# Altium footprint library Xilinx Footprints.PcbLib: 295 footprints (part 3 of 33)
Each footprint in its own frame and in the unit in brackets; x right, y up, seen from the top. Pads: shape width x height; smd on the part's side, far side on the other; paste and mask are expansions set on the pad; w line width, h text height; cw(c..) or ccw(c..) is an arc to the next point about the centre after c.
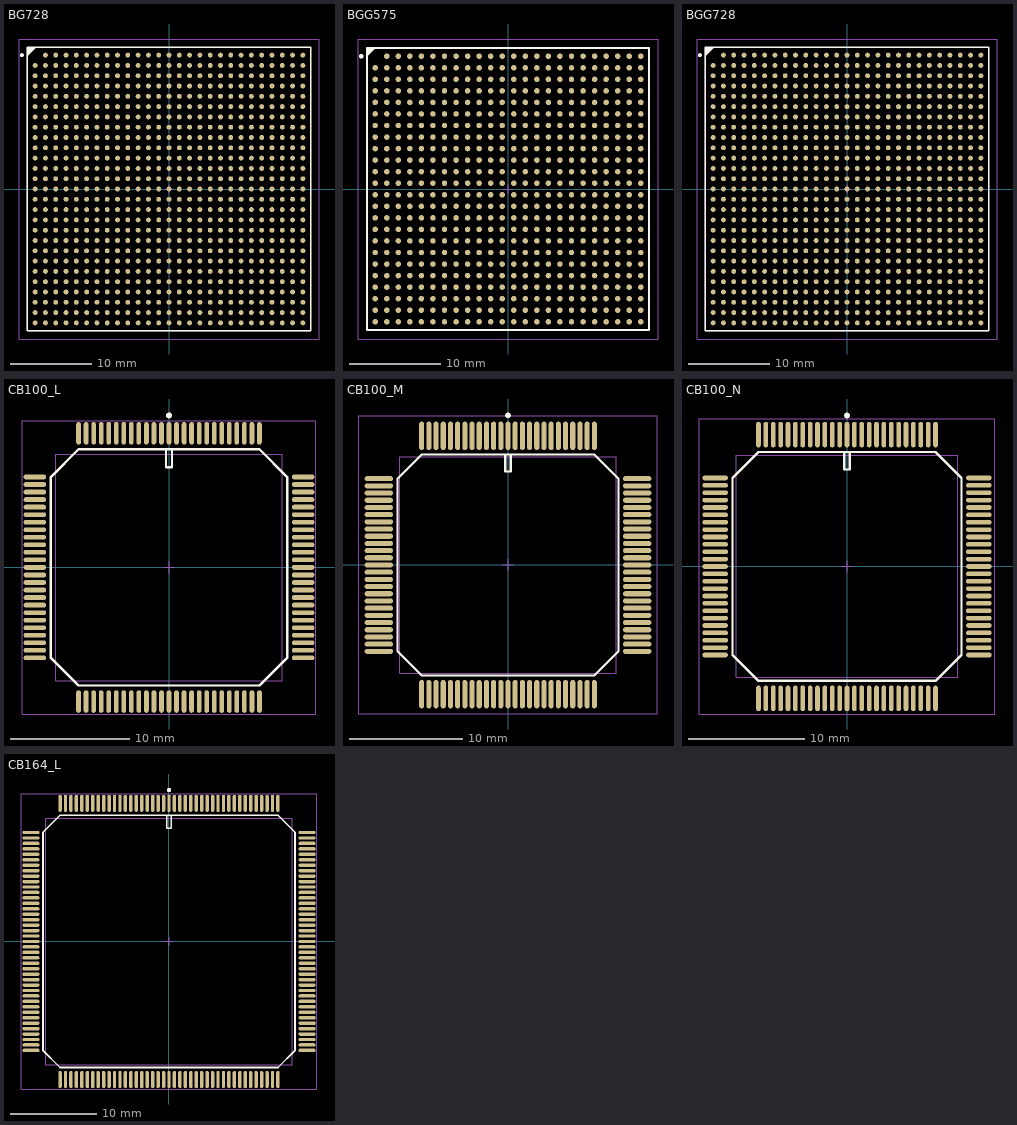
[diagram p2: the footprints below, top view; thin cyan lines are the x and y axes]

## BG728 [mm] "728-Ball Plastic Ball Grid Array (BG728)"
height 2.6
pads (728):
  round 0.6 smd: A2(-15.24,16.51) A3(-13.97,16.51) A4(-12.7,16.51) A5(-11.43,16.51) A6(-10.16,16.51) A7(-8.89,16.51) A8(-7.62,16.51) A9(-6.35,16.51) A10(-5.08,16.51) A11(-3.81,16.51) A12(-2.54,16.51) A13(-1.27,16.51) A14(0,16.51) A15(1.27,16.51) A16(2.54,16.51) A17(3.81,16.51) A18(5.08,16.51) A19(6.35,16.51) A20(7.62,16.51) A21(8.89,16.51) A22(10.16,16.51) A23(11.43,16.51) A24(12.7,16.51) A25(13.97,16.51) A26(15.24,16.51) A27(16.51,16.51) AA1(-16.51,-8.89) AA2(-15.24,-8.89) AA3(-13.97,-8.89) AA4(-12.7,-8.89) AA5(-11.43,-8.89) AA6(-10.16,-8.89) AA7(-8.89,-8.89) AA8(-7.62,-8.89) AA9(-6.35,-8.89) AA10(-5.08,-8.89) AA11(-3.81,-8.89) AA12(-2.54,-8.89) AA13(-1.27,-8.89) AA14(0,-8.89) AA15(1.27,-8.89) AA16(2.54,-8.89) AA17(3.81,-8.89) AA18(5.08,-8.89) AA19(6.35,-8.89) AA20(7.62,-8.89) AA21(8.89,-8.89) AA22(10.16,-8.89) AA23(11.43,-8.89) AA24(12.7,-8.89) AA25(13.97,-8.89) AA26(15.24,-8.89) AA27(16.51,-8.89) AB1(-16.51,-10.16) AB2(-15.24,-10.16) AB3(-13.97,-10.16) AB4(-12.7,-10.16) AB5(-11.43,-10.16) AB6(-10.16,-10.16) AB7(-8.89,-10.16) AB8(-7.62,-10.16) AB9(-6.35,-10.16) AB10(-5.08,-10.16) AB11(-3.81,-10.16) AB12(-2.54,-10.16) AB13(-1.27,-10.16) AB14(0,-10.16) AB15(1.27,-10.16) AB16(2.54,-10.16) AB17(3.81,-10.16) AB18(5.08,-10.16) AB19(6.35,-10.16) AB20(7.62,-10.16) AB21(8.89,-10.16) AB22(10.16,-10.16) AB23(11.43,-10.16) AB24(12.7,-10.16) AB25(13.97,-10.16) AB26(15.24,-10.16) AB27(16.51,-10.16) AC1(-16.51,-11.43) AC2(-15.24,-11.43) AC3(-13.97,-11.43) AC4(-12.7,-11.43) AC5(-11.43,-11.43) AC6(-10.16,-11.43) AC7(-8.89,-11.43) AC8(-7.62,-11.43) AC9(-6.35,-11.43) AC10(-5.08,-11.43) AC11(-3.81,-11.43) AC12(-2.54,-11.43) AC13(-1.27,-11.43) AC14(0,-11.43) AC15(1.27,-11.43) AC16(2.54,-11.43) AC17(3.81,-11.43) AC18(5.08,-11.43) AC19(6.35,-11.43) AC20(7.62,-11.43) AC21(8.89,-11.43) AC22(10.16,-11.43) AC23(11.43,-11.43) AC24(12.7,-11.43) AC25(13.97,-11.43) AC26(15.24,-11.43) AC27(16.51,-11.43) AD1(-16.51,-12.7) AD2(-15.24,-12.7) AD3(-13.97,-12.7) AD4(-12.7,-12.7) AD5(-11.43,-12.7) AD6(-10.16,-12.7) AD7(-8.89,-12.7) AD8(-7.62,-12.7) AD9(-6.35,-12.7) AD10(-5.08,-12.7) AD11(-3.81,-12.7) AD12(-2.54,-12.7) AD13(-1.27,-12.7) AD14(0,-12.7) AD15(1.27,-12.7) AD16(2.54,-12.7) AD17(3.81,-12.7) AD18(5.08,-12.7) AD19(6.35,-12.7) AD20(7.62,-12.7) AD21(8.89,-12.7) AD22(10.16,-12.7) AD23(11.43,-12.7) AD24(12.7,-12.7) AD25(13.97,-12.7) AD26(15.24,-12.7) AD27(16.51,-12.7) AE1(-16.51,-13.97) AE2(-15.24,-13.97) AE3(-13.97,-13.97) AE4(-12.7,-13.97) AE5(-11.43,-13.97) AE6(-10.16,-13.97) AE7(-8.89,-13.97) AE8(-7.62,-13.97) AE9(-6.35,-13.97) AE10(-5.08,-13.97) AE11(-3.81,-13.97) AE12(-2.54,-13.97) AE13(-1.27,-13.97) AE14(0,-13.97) AE15(1.27,-13.97) AE16(2.54,-13.97) AE17(3.81,-13.97) AE18(5.08,-13.97) AE19(6.35,-13.97) AE20(7.62,-13.97) AE21(8.89,-13.97) AE22(10.16,-13.97) AE23(11.43,-13.97) AE24(12.7,-13.97) AE25(13.97,-13.97) AE26(15.24,-13.97) AE27(16.51,-13.97) AF1(-16.51,-15.24) AF2(-15.24,-15.24) AF3(-13.97,-15.24) AF4(-12.7,-15.24) AF5(-11.43,-15.24) AF6(-10.16,-15.24) AF7(-8.89,-15.24) AF8(-7.62,-15.24) AF9(-6.35,-15.24) AF10(-5.08,-15.24) AF11(-3.81,-15.24) AF12(-2.54,-15.24) AF13(-1.27,-15.24) AF14(0,-15.24) AF15(1.27,-15.24) AF16(2.54,-15.24) AF17(3.81,-15.24) AF18(5.08,-15.24) AF19(6.35,-15.24) AF20(7.62,-15.24) AF21(8.89,-15.24) AF22(10.16,-15.24) AF23(11.43,-15.24) AF24(12.7,-15.24) AF25(13.97,-15.24) AF26(15.24,-15.24) AF27(16.51,-15.24) AG1(-16.51,-16.51) AG2(-15.24,-16.51) AG3(-13.97,-16.51) AG4(-12.7,-16.51) AG5(-11.43,-16.51) AG6(-10.16,-16.51) AG7(-8.89,-16.51) AG8(-7.62,-16.51) AG9(-6.35,-16.51) AG10(-5.08,-16.51) AG11(-3.81,-16.51) AG12(-2.54,-16.51) AG13(-1.27,-16.51) AG14(0,-16.51) AG15(1.27,-16.51) AG16(2.54,-16.51) AG17(3.81,-16.51) AG18(5.08,-16.51) AG19(6.35,-16.51) AG20(7.62,-16.51) AG21(8.89,-16.51) AG22(10.16,-16.51) AG23(11.43,-16.51) AG24(12.7,-16.51) AG25(13.97,-16.51) AG26(15.24,-16.51) AG27(16.51,-16.51) B1(-16.51,15.24) B2(-15.24,15.24) B3(-13.97,15.24) B4(-12.7,15.24) B5(-11.43,15.24) B6(-10.16,15.24) B7(-8.89,15.24) B8(-7.62,15.24) B9(-6.35,15.24) B10(-5.08,15.24) B11(-3.81,15.24) B12(-2.54,15.24) B13(-1.27,15.24) B14(0,15.24) B15(1.27,15.24) B16(2.54,15.24) B17(3.81,15.24) B18(5.08,15.24) B19(6.35,15.24) B20(7.62,15.24) B21(8.89,15.24) B22(10.16,15.24) B23(11.43,15.24) B24(12.7,15.24) B25(13.97,15.24) B26(15.24,15.24) B27(16.51,15.24) C1(-16.51,13.97) C2(-15.24,13.97) C3(-13.97,13.97) C4(-12.7,13.97) C5(-11.43,13.97) C6(-10.16,13.97) C7(-8.89,13.97) C8(-7.62,13.97) C9(-6.35,13.97) C10(-5.08,13.97) C11(-3.81,13.97) C12(-2.54,13.97) C13(-1.27,13.97) C14(0,13.97) C15(1.27,13.97) C16(2.54,13.97) C17(3.81,13.97) C18(5.08,13.97) C19(6.35,13.97) C20(7.62,13.97) C21(8.89,13.97) C22(10.16,13.97) C23(11.43,13.97) C24(12.7,13.97) C25(13.97,13.97) C26(15.24,13.97) C27(16.51,13.97) D1(-16.51,12.7) D2(-15.24,12.7) D3(-13.97,12.7) D4(-12.7,12.7) D5(-11.43,12.7) D6(-10.16,12.7) D7(-8.89,12.7) D8(-7.62,12.7) D9(-6.35,12.7) D10(-5.08,12.7) D11(-3.81,12.7) D12(-2.54,12.7) D13(-1.27,12.7) D14(0,12.7) D15(1.27,12.7) D16(2.54,12.7) D17(3.81,12.7) D18(5.08,12.7) D19(6.35,12.7) D20(7.62,12.7) D21(8.89,12.7) D22(10.16,12.7) D23(11.43,12.7) D24(12.7,12.7) D25(13.97,12.7) D26(15.24,12.7) D27(16.51,12.7) E1(-16.51,11.43) E2(-15.24,11.43) E3(-13.97,11.43) E4(-12.7,11.43) E5(-11.43,11.43) E6(-10.16,11.43) E7(-8.89,11.43) E8(-7.62,11.43) E9(-6.35,11.43) E10(-5.08,11.43) E11(-3.81,11.43) E12(-2.54,11.43) E13(-1.27,11.43) E14(0,11.43) E15(1.27,11.43) E16(2.54,11.43) E17(3.81,11.43) E18(5.08,11.43) E19(6.35,11.43) E20(7.62,11.43) E21(8.89,11.43) E22(10.16,11.43) E23(11.43,11.43) E24(12.7,11.43) E25(13.97,11.43) E26(15.24,11.43) E27(16.51,11.43) F1(-16.51,10.16) F2(-15.24,10.16) F3(-13.97,10.16) F4(-12.7,10.16) F5(-11.43,10.16) F6(-10.16,10.16) F7(-8.89,10.16) F8(-7.62,10.16) F9(-6.35,10.16) F10(-5.08,10.16) F11(-3.81,10.16) F12(-2.54,10.16) F13(-1.27,10.16) F14(0,10.16) F15(1.27,10.16) F16(2.54,10.16) F17(3.81,10.16) F18(5.08,10.16) F19(6.35,10.16) F20(7.62,10.16) F21(8.89,10.16) F22(10.16,10.16) F23(11.43,10.16) F24(12.7,10.16) F25(13.97,10.16) F26(15.24,10.16) F27(16.51,10.16) G1(-16.51,8.89) G2(-15.24,8.89) G3(-13.97,8.89) G4(-12.7,8.89) G5(-11.43,8.89) G6(-10.16,8.89) G7(-8.89,8.89) G8(-7.62,8.89) G9(-6.35,8.89) G10(-5.08,8.89) G11(-3.81,8.89) G12(-2.54,8.89) G13(-1.27,8.89) G14(0,8.89) G15(1.27,8.89) G16(2.54,8.89) G17(3.81,8.89) G18(5.08,8.89) G19(6.35,8.89) G20(7.62,8.89) G21(8.89,8.89) G22(10.16,8.89) G23(11.43,8.89) G24(12.7,8.89) G25(13.97,8.89) G26(15.24,8.89) G27(16.51,8.89) H1(-16.51,7.62) H2(-15.24,7.62) H3(-13.97,7.62) H4(-12.7,7.62) H5(-11.43,7.62) H6(-10.16,7.62) H7(-8.89,7.62) H8(-7.62,7.62) H9(-6.35,7.62) H10(-5.08,7.62) H11(-3.81,7.62) H12(-2.54,7.62) H13(-1.27,7.62) H14(0,7.62) H15(1.27,7.62) H16(2.54,7.62) H17(3.81,7.62) H18(5.08,7.62) H19(6.35,7.62) H20(7.62,7.62) H21(8.89,7.62) H22(10.16,7.62) H23(11.43,7.62) H24(12.7,7.62) H25(13.97,7.62) H26(15.24,7.62) H27(16.51,7.62) J1(-16.51,6.35) J2(-15.24,6.35) J3(-13.97,6.35) J4(-12.7,6.35) J5(-11.43,6.35) J6(-10.16,6.35) J7(-8.89,6.35) J8(-7.62,6.35) J9(-6.35,6.35) J10(-5.08,6.35) J11(-3.81,6.35) J12(-2.54,6.35) J13(-1.27,6.35) J14(0,6.35) J15(1.27,6.35) J16(2.54,6.35) J17(3.81,6.35) J18(5.08,6.35) J19(6.35,6.35) J20(7.62,6.35) J21(8.89,6.35) J22(10.16,6.35) J23(11.43,6.35) J24(12.7,6.35) J25(13.97,6.35) J26(15.24,6.35) J27(16.51,6.35) K1(-16.51,5.08) K2(-15.24,5.08) K3(-13.97,5.08) K4(-12.7,5.08) K5(-11.43,5.08) K6(-10.16,5.08) K7(-8.89,5.08) K8(-7.62,5.08) K9(-6.35,5.08) K10(-5.08,5.08) K11(-3.81,5.08) K12(-2.54,5.08) K13(-1.27,5.08) K14(0,5.08) K15(1.27,5.08) K16(2.54,5.08) K17(3.81,5.08) K18(5.08,5.08) K19(6.35,5.08) K20(7.62,5.08) K21(8.89,5.08) K22(10.16,5.08) K23(11.43,5.08) K24(12.7,5.08) K25(13.97,5.08) K26(15.24,5.08) K27(16.51,5.08) L1(-16.51,3.81) L2(-15.24,3.81) L3(-13.97,3.81) L4(-12.7,3.81) L5(-11.43,3.81) L6(-10.16,3.81) L7(-8.89,3.81) L8(-7.62,3.81) L9(-6.35,3.81) L10(-5.08,3.81) L11(-3.81,3.81) L12(-2.54,3.81) L13(-1.27,3.81) L14(0,3.81) L15(1.27,3.81) L16(2.54,3.81) L17(3.81,3.81) L18(5.08,3.81) L19(6.35,3.81) L20(7.62,3.81) L21(8.89,3.81) L22(10.16,3.81) L23(11.43,3.81) L24(12.7,3.81) L25(13.97,3.81) L26(15.24,3.81) L27(16.51,3.81) M1(-16.51,2.54) M2(-15.24,2.54) M3(-13.97,2.54) M4(-12.7,2.54) M5(-11.43,2.54) M6(-10.16,2.54) M7(-8.89,2.54) M8(-7.62,2.54) M9(-6.35,2.54) M10(-5.08,2.54) M11(-3.81,2.54) M12(-2.54,2.54) M13(-1.27,2.54) M14(0,2.54) M15(1.27,2.54) M16(2.54,2.54) M17(3.81,2.54) M18(5.08,2.54) M19(6.35,2.54) M20(7.62,2.54) M21(8.89,2.54) M22(10.16,2.54) M23(11.43,2.54) M24(12.7,2.54) M25(13.97,2.54) M26(15.24,2.54) M27(16.51,2.54) N1(-16.51,1.27) N2(-15.24,1.27) N3(-13.97,1.27) N4(-12.7,1.27) N5(-11.43,1.27) N6(-10.16,1.27) N7(-8.89,1.27) N8(-7.62,1.27) N9(-6.35,1.27) N10(-5.08,1.27) N11(-3.81,1.27) N12(-2.54,1.27) N13(-1.27,1.27) N14(0,1.27) N15(1.27,1.27) N16(2.54,1.27) N17(3.81,1.27) N18(5.08,1.27) N19(6.35,1.27) N20(7.62,1.27) N21(8.89,1.27) N22(10.16,1.27) N23(11.43,1.27) N24(12.7,1.27) N25(13.97,1.27) N26(15.24,1.27) N27(16.51,1.27) P1(-16.51,0) P2(-15.24,0) P3(-13.97,0) P4(-12.7,0) P5(-11.43,0) P6(-10.16,0) P7(-8.89,0) P8(-7.62,0) P9(-6.35,0) P10(-5.08,0) P11(-3.81,0) P12(-2.54,0) P13(-1.27,0) P14(0,0) P15(1.27,0) P16(2.54,0) P17(3.81,0) P18(5.08,0) P19(6.35,0) P20(7.62,0) P21(8.89,0) P22(10.16,0) P23(11.43,0) P24(12.7,0) P25(13.97,0) P26(15.24,0) P27(16.51,0) R1(-16.51,-1.27) R2(-15.24,-1.27) R3(-13.97,-1.27) R4(-12.7,-1.27) R5(-11.43,-1.27) R6(-10.16,-1.27) R7(-8.89,-1.27) R8(-7.62,-1.27) R9(-6.35,-1.27) R10(-5.08,-1.27) R11(-3.81,-1.27) R12(-2.54,-1.27) R13(-1.27,-1.27) R14(0,-1.27) R15(1.27,-1.27) R16(2.54,-1.27) R17(3.81,-1.27) R18(5.08,-1.27) R19(6.35,-1.27) R20(7.62,-1.27) R21(8.89,-1.27) R22(10.16,-1.27) R23(11.43,-1.27) R24(12.7,-1.27) R25(13.97,-1.27) R26(15.24,-1.27) R27(16.51,-1.27) T1(-16.51,-2.54) T2(-15.24,-2.54) T3(-13.97,-2.54) T4(-12.7,-2.54) T5(-11.43,-2.54) T6(-10.16,-2.54) T7(-8.89,-2.54) T8(-7.62,-2.54) T9(-6.35,-2.54) T10(-5.08,-2.54) T11(-3.81,-2.54) T12(-2.54,-2.54) T13(-1.27,-2.54) T14(0,-2.54) T15(1.27,-2.54) T16(2.54,-2.54) T17(3.81,-2.54) T18(5.08,-2.54) T19(6.35,-2.54) T20(7.62,-2.54) T21(8.89,-2.54) T22(10.16,-2.54) T23(11.43,-2.54) T24(12.7,-2.54) T25(13.97,-2.54) T26(15.24,-2.54) T27(16.51,-2.54) U1(-16.51,-3.81) U2(-15.24,-3.81) U3(-13.97,-3.81) U4(-12.7,-3.81) U5(-11.43,-3.81) U6(-10.16,-3.81) U7(-8.89,-3.81) U8(-7.62,-3.81) U9(-6.35,-3.81) U10(-5.08,-3.81) U11(-3.81,-3.81) U12(-2.54,-3.81) U13(-1.27,-3.81) U14(0,-3.81) U15(1.27,-3.81) U16(2.54,-3.81) U17(3.81,-3.81) U18(5.08,-3.81) U19(6.35,-3.81) U20(7.62,-3.81) U21(8.89,-3.81) U22(10.16,-3.81) U23(11.43,-3.81) U24(12.7,-3.81) U25(13.97,-3.81) U26(15.24,-3.81) U27(16.51,-3.81) V1(-16.51,-5.08) V2(-15.24,-5.08) V3(-13.97,-5.08) V4(-12.7,-5.08) V5(-11.43,-5.08) V6(-10.16,-5.08) V7(-8.89,-5.08) V8(-7.62,-5.08) V9(-6.35,-5.08) V10(-5.08,-5.08) V11(-3.81,-5.08) V12(-2.54,-5.08) V13(-1.27,-5.08) V14(0,-5.08) V15(1.27,-5.08) V16(2.54,-5.08) V17(3.81,-5.08) V18(5.08,-5.08) V19(6.35,-5.08) V20(7.62,-5.08) V21(8.89,-5.08) V22(10.16,-5.08) V23(11.43,-5.08) V24(12.7,-5.08) V25(13.97,-5.08) V26(15.24,-5.08) V27(16.51,-5.08) W1(-16.51,-6.35) W2(-15.24,-6.35) W3(-13.97,-6.35) W4(-12.7,-6.35) W5(-11.43,-6.35) W6(-10.16,-6.35) W7(-8.89,-6.35) W8(-7.62,-6.35) W9(-6.35,-6.35) W10(-5.08,-6.35) W11(-3.81,-6.35) W12(-2.54,-6.35) W13(-1.27,-6.35) W14(0,-6.35) W15(1.27,-6.35) W16(2.54,-6.35) W17(3.81,-6.35) W18(5.08,-6.35) W19(6.35,-6.35) W20(7.62,-6.35) W21(8.89,-6.35) W22(10.16,-6.35) W23(11.43,-6.35) W24(12.7,-6.35) W25(13.97,-6.35) W26(15.24,-6.35) W27(16.51,-6.35) Y1(-16.51,-7.62) Y2(-15.24,-7.62) Y3(-13.97,-7.62) Y4(-12.7,-7.62) Y5(-11.43,-7.62) Y6(-10.16,-7.62) Y7(-8.89,-7.62) Y8(-7.62,-7.62) Y9(-6.35,-7.62) Y10(-5.08,-7.62) Y11(-3.81,-7.62) Y12(-2.54,-7.62) Y13(-1.27,-7.62) Y14(0,-7.62) Y15(1.27,-7.62) Y16(2.54,-7.62) Y17(3.81,-7.62) Y18(5.08,-7.62) Y19(6.35,-7.62) Y20(7.62,-7.62) Y21(8.89,-7.62) Y22(10.16,-7.62) Y23(11.43,-7.62) Y24(12.7,-7.62) Y25(13.97,-7.62) Y26(15.24,-7.62) Y27(16.51,-7.62)
Top Overlay:
  circle w0.25: c-18.15,16.51 r0.125
  region: -16.51,17.5 -17.5,16.51 -17.5,17.5
  lines w0.2: -17.5,16.51 -16.51,17.5 ; -17.5,-17.5 17.5,-17.5 17.5,17.5 -17.5,17.5 -17.5,-17.5
Mechanical 13:
  lines w0.1: -17.5,-17.5 17.5,-17.5 17.5,17.5 -17.5,17.5 -17.5,-17.5
Mechanical 15:
  lines w0.1: -0.5,0 0.5,0 ; 0,-0.5 0,0.5 ; -18.5,-18.5 18.5,-18.5 18.5,18.5 -18.5,18.5 -18.5,-18.5
3D body: height 2.6, standoff 0, extent -17.5,-17.5 17.5,17.5

## BGG575 [mm] "575-Ball Molded Ball Grid Array (BGG575) - Pb-Free"
height 2.6
pads (575):
  round 0.6 smd: A2(-13.335,14.605) A3(-12.065,14.605) A4(-10.795,14.605) A5(-9.525,14.605) A6(-8.255,14.605) A7(-6.985,14.605) A8(-5.715,14.605) A9(-4.445,14.605) A10(-3.175,14.605) A11(-1.905,14.605) A12(-0.635,14.605) A13(0.635,14.605) A14(1.905,14.605) A15(3.175,14.605) A16(4.445,14.605) A17(5.715,14.605) A18(6.985,14.605) A19(8.255,14.605) A20(9.525,14.605) A21(10.795,14.605) A22(12.065,14.605) A23(13.335,14.605) A24(14.605,14.605) AA1(-14.605,-10.795) AA2(-13.335,-10.795) AA3(-12.065,-10.795) AA4(-10.795,-10.795) AA5(-9.525,-10.795) AA6(-8.255,-10.795) AA7(-6.985,-10.795) AA8(-5.715,-10.795) AA9(-4.445,-10.795) AA10(-3.175,-10.795) AA11(-1.905,-10.795) AA12(-0.635,-10.795) AA13(0.635,-10.795) AA14(1.905,-10.795) AA15(3.175,-10.795) AA16(4.445,-10.795) AA17(5.715,-10.795) AA18(6.985,-10.795) AA19(8.255,-10.795) AA20(9.525,-10.795) AA21(10.795,-10.795) AA22(12.065,-10.795) AA23(13.335,-10.795) AA24(14.605,-10.795) AB1(-14.605,-12.065) AB2(-13.335,-12.065) AB3(-12.065,-12.065) AB4(-10.795,-12.065) AB5(-9.525,-12.065) AB6(-8.255,-12.065) AB7(-6.985,-12.065) AB8(-5.715,-12.065) AB9(-4.445,-12.065) AB10(-3.175,-12.065) AB11(-1.905,-12.065) AB12(-0.635,-12.065) AB13(0.635,-12.065) AB14(1.905,-12.065) AB15(3.175,-12.065) AB16(4.445,-12.065) AB17(5.715,-12.065) AB18(6.985,-12.065) AB19(8.255,-12.065) AB20(9.525,-12.065) AB21(10.795,-12.065) AB22(12.065,-12.065) AB23(13.335,-12.065) AB24(14.605,-12.065) AC1(-14.605,-13.335) AC2(-13.335,-13.335) AC3(-12.065,-13.335) AC4(-10.795,-13.335) AC5(-9.525,-13.335) AC6(-8.255,-13.335) AC7(-6.985,-13.335) AC8(-5.715,-13.335) AC9(-4.445,-13.335) AC10(-3.175,-13.335) AC11(-1.905,-13.335) AC12(-0.635,-13.335) AC13(0.635,-13.335) AC14(1.905,-13.335) AC15(3.175,-13.335) AC16(4.445,-13.335) AC17(5.715,-13.335) AC18(6.985,-13.335) AC19(8.255,-13.335) AC20(9.525,-13.335) AC21(10.795,-13.335) AC22(12.065,-13.335) AC23(13.335,-13.335) AC24(14.605,-13.335) AD1(-14.605,-14.605) AD2(-13.335,-14.605) AD3(-12.065,-14.605) AD4(-10.795,-14.605) AD5(-9.525,-14.605) AD6(-8.255,-14.605) AD7(-6.985,-14.605) AD8(-5.715,-14.605) AD9(-4.445,-14.605) AD10(-3.175,-14.605) AD11(-1.905,-14.605) AD12(-0.635,-14.605) AD13(0.635,-14.605) AD14(1.905,-14.605) AD15(3.175,-14.605) AD16(4.445,-14.605) AD17(5.715,-14.605) AD18(6.985,-14.605) AD19(8.255,-14.605) AD20(9.525,-14.605) AD21(10.795,-14.605) AD22(12.065,-14.605) AD23(13.335,-14.605) AD24(14.605,-14.605) B1(-14.605,13.335) B2(-13.335,13.335) B3(-12.065,13.335) B4(-10.795,13.335) B5(-9.525,13.335) B6(-8.255,13.335) B7(-6.985,13.335) B8(-5.715,13.335) B9(-4.445,13.335) B10(-3.175,13.335) B11(-1.905,13.335) B12(-0.635,13.335) B13(0.635,13.335) B14(1.905,13.335) B15(3.175,13.335) B16(4.445,13.335) B17(5.715,13.335) B18(6.985,13.335) B19(8.255,13.335) B20(9.525,13.335) B21(10.795,13.335) B22(12.065,13.335) B23(13.335,13.335) B24(14.605,13.335) C1(-14.605,12.065) C2(-13.335,12.065) C3(-12.065,12.065) C4(-10.795,12.065) C5(-9.525,12.065) C6(-8.255,12.065) C7(-6.985,12.065) C8(-5.715,12.065) C9(-4.445,12.065) C10(-3.175,12.065) C11(-1.905,12.065) C12(-0.635,12.065) C13(0.635,12.065) C14(1.905,12.065) C15(3.175,12.065) C16(4.445,12.065) C17(5.715,12.065) C18(6.985,12.065) C19(8.255,12.065) C20(9.525,12.065) C21(10.795,12.065) C22(12.065,12.065) C23(13.335,12.065) C24(14.605,12.065) D1(-14.605,10.795) D2(-13.335,10.795) D3(-12.065,10.795) D4(-10.795,10.795) D5(-9.525,10.795) D6(-8.255,10.795) D7(-6.985,10.795) D8(-5.715,10.795) D9(-4.445,10.795) D10(-3.175,10.795) D11(-1.905,10.795) D12(-0.635,10.795) D13(0.635,10.795) D14(1.905,10.795) D15(3.175,10.795) D16(4.445,10.795) D17(5.715,10.795) D18(6.985,10.795) D19(8.255,10.795) D20(9.525,10.795) D21(10.795,10.795) D22(12.065,10.795) D23(13.335,10.795) D24(14.605,10.795) E1(-14.605,9.525) E2(-13.335,9.525) E3(-12.065,9.525) E4(-10.795,9.525) E5(-9.525,9.525) E6(-8.255,9.525) E7(-6.985,9.525) E8(-5.715,9.525) E9(-4.445,9.525) E10(-3.175,9.525) E11(-1.905,9.525) E12(-0.635,9.525) E13(0.635,9.525) E14(1.905,9.525) E15(3.175,9.525) E16(4.445,9.525) E17(5.715,9.525) E18(6.985,9.525) E19(8.255,9.525) E20(9.525,9.525) E21(10.795,9.525) E22(12.065,9.525) E23(13.335,9.525) E24(14.605,9.525) F1(-14.605,8.255) F2(-13.335,8.255) F3(-12.065,8.255) F4(-10.795,8.255) F5(-9.525,8.255) F6(-8.255,8.255) F7(-6.985,8.255) F8(-5.715,8.255) F9(-4.445,8.255) F10(-3.175,8.255) F11(-1.905,8.255) F12(-0.635,8.255) F13(0.635,8.255) F14(1.905,8.255) F15(3.175,8.255) F16(4.445,8.255) F17(5.715,8.255) F18(6.985,8.255) F19(8.255,8.255) F20(9.525,8.255) F21(10.795,8.255) F22(12.065,8.255) F23(13.335,8.255) F24(14.605,8.255) G1(-14.605,6.985) G2(-13.335,6.985) G3(-12.065,6.985) G4(-10.795,6.985) G5(-9.525,6.985) G6(-8.255,6.985) G7(-6.985,6.985) G8(-5.715,6.985) G9(-4.445,6.985) G10(-3.175,6.985) G11(-1.905,6.985) G12(-0.635,6.985) G13(0.635,6.985) G14(1.905,6.985) G15(3.175,6.985) G16(4.445,6.985) G17(5.715,6.985) G18(6.985,6.985) G19(8.255,6.985) G20(9.525,6.985) G21(10.795,6.985) G22(12.065,6.985) G23(13.335,6.985) G24(14.605,6.985) H1(-14.605,5.715) H2(-13.335,5.715) H3(-12.065,5.715) H4(-10.795,5.715) H5(-9.525,5.715) H6(-8.255,5.715) H7(-6.985,5.715) H8(-5.715,5.715) H9(-4.445,5.715) H10(-3.175,5.715) H11(-1.905,5.715) H12(-0.635,5.715) H13(0.635,5.715) H14(1.905,5.715) H15(3.175,5.715) H16(4.445,5.715) H17(5.715,5.715) H18(6.985,5.715) H19(8.255,5.715) H20(9.525,5.715) H21(10.795,5.715) H22(12.065,5.715) H23(13.335,5.715) H24(14.605,5.715) J1(-14.605,4.445) J2(-13.335,4.445) J3(-12.065,4.445) J4(-10.795,4.445) J5(-9.525,4.445) J6(-8.255,4.445) J7(-6.985,4.445) J8(-5.715,4.445) J9(-4.445,4.445) J10(-3.175,4.445) J11(-1.905,4.445) J12(-0.635,4.445) J13(0.635,4.445) J14(1.905,4.445) J15(3.175,4.445) J16(4.445,4.445) J17(5.715,4.445) J18(6.985,4.445) J19(8.255,4.445) J20(9.525,4.445) J21(10.795,4.445) J22(12.065,4.445) J23(13.335,4.445) J24(14.605,4.445) K1(-14.605,3.175) K2(-13.335,3.175) K3(-12.065,3.175) K4(-10.795,3.175) K5(-9.525,3.175) K6(-8.255,3.175) K7(-6.985,3.175) K8(-5.715,3.175) K9(-4.445,3.175) K10(-3.175,3.175) K11(-1.905,3.175) K12(-0.635,3.175) K13(0.635,3.175) K14(1.905,3.175) K15(3.175,3.175) K16(4.445,3.175) K17(5.715,3.175) K18(6.985,3.175) K19(8.255,3.175) K20(9.525,3.175) K21(10.795,3.175) K22(12.065,3.175) K23(13.335,3.175) K24(14.605,3.175) L1(-14.605,1.905) L2(-13.335,1.905) L3(-12.065,1.905) L4(-10.795,1.905) L5(-9.525,1.905) L6(-8.255,1.905) L7(-6.985,1.905) L8(-5.715,1.905) L9(-4.445,1.905) L10(-3.175,1.905) L11(-1.905,1.905) L12(-0.635,1.905) L13(0.635,1.905) L14(1.905,1.905) L15(3.175,1.905) L16(4.445,1.905) L17(5.715,1.905) L18(6.985,1.905) L19(8.255,1.905) L20(9.525,1.905) L21(10.795,1.905) L22(12.065,1.905) L23(13.335,1.905) L24(14.605,1.905) M1(-14.605,0.635) M2(-13.335,0.635) M3(-12.065,0.635) M4(-10.795,0.635) M5(-9.525,0.635) M6(-8.255,0.635) M7(-6.985,0.635) M8(-5.715,0.635) M9(-4.445,0.635) M10(-3.175,0.635) M11(-1.905,0.635) M12(-0.635,0.635) M13(0.635,0.635) M14(1.905,0.635) M15(3.175,0.635) M16(4.445,0.635) M17(5.715,0.635) M18(6.985,0.635) M19(8.255,0.635) M20(9.525,0.635) M21(10.795,0.635) M22(12.065,0.635) M23(13.335,0.635) M24(14.605,0.635) N1(-14.605,-0.635) N2(-13.335,-0.635) N3(-12.065,-0.635) N4(-10.795,-0.635) N5(-9.525,-0.635) N6(-8.255,-0.635) N7(-6.985,-0.635) N8(-5.715,-0.635) N9(-4.445,-0.635) N10(-3.175,-0.635) N11(-1.905,-0.635) N12(-0.635,-0.635) N13(0.635,-0.635) N14(1.905,-0.635) N15(3.175,-0.635) N16(4.445,-0.635) N17(5.715,-0.635) N18(6.985,-0.635) N19(8.255,-0.635) N20(9.525,-0.635) N21(10.795,-0.635) N22(12.065,-0.635) N23(13.335,-0.635) N24(14.605,-0.635) P1(-14.605,-1.905) P2(-13.335,-1.905) P3(-12.065,-1.905) P4(-10.795,-1.905) P5(-9.525,-1.905) P6(-8.255,-1.905) P7(-6.985,-1.905) P8(-5.715,-1.905) P9(-4.445,-1.905) P10(-3.175,-1.905) P11(-1.905,-1.905) P12(-0.635,-1.905) P13(0.635,-1.905) P14(1.905,-1.905) P15(3.175,-1.905) P16(4.445,-1.905) P17(5.715,-1.905) P18(6.985,-1.905) P19(8.255,-1.905) P20(9.525,-1.905) P21(10.795,-1.905) P22(12.065,-1.905) P23(13.335,-1.905) P24(14.605,-1.905) R1(-14.605,-3.175) R2(-13.335,-3.175) R3(-12.065,-3.175) R4(-10.795,-3.175) R5(-9.525,-3.175) R6(-8.255,-3.175) R7(-6.985,-3.175) R8(-5.715,-3.175) R9(-4.445,-3.175) R10(-3.175,-3.175) R11(-1.905,-3.175) R12(-0.635,-3.175) R13(0.635,-3.175) R14(1.905,-3.175) R15(3.175,-3.175) R16(4.445,-3.175) R17(5.715,-3.175) R18(6.985,-3.175) R19(8.255,-3.175) R20(9.525,-3.175) R21(10.795,-3.175) R22(12.065,-3.175) R23(13.335,-3.175) R24(14.605,-3.175) T1(-14.605,-4.445) T2(-13.335,-4.445) T3(-12.065,-4.445) T4(-10.795,-4.445) T5(-9.525,-4.445) T6(-8.255,-4.445) T7(-6.985,-4.445) T8(-5.715,-4.445) T9(-4.445,-4.445) T10(-3.175,-4.445) T11(-1.905,-4.445) T12(-0.635,-4.445) T13(0.635,-4.445) T14(1.905,-4.445) T15(3.175,-4.445) T16(4.445,-4.445) T17(5.715,-4.445) T18(6.985,-4.445) T19(8.255,-4.445) T20(9.525,-4.445) T21(10.795,-4.445) T22(12.065,-4.445) T23(13.335,-4.445) T24(14.605,-4.445) U1(-14.605,-5.715) U2(-13.335,-5.715) U3(-12.065,-5.715) U4(-10.795,-5.715) U5(-9.525,-5.715) U6(-8.255,-5.715) U7(-6.985,-5.715) U8(-5.715,-5.715) U9(-4.445,-5.715) U10(-3.175,-5.715) U11(-1.905,-5.715) U12(-0.635,-5.715) U13(0.635,-5.715) U14(1.905,-5.715) U15(3.175,-5.715) U16(4.445,-5.715) U17(5.715,-5.715) U18(6.985,-5.715) U19(8.255,-5.715) U20(9.525,-5.715) U21(10.795,-5.715) U22(12.065,-5.715) U23(13.335,-5.715) U24(14.605,-5.715) V1(-14.605,-6.985) V2(-13.335,-6.985) V3(-12.065,-6.985) V4(-10.795,-6.985) V5(-9.525,-6.985) V6(-8.255,-6.985) V7(-6.985,-6.985) V8(-5.715,-6.985) V9(-4.445,-6.985) V10(-3.175,-6.985) V11(-1.905,-6.985) V12(-0.635,-6.985) V13(0.635,-6.985) V14(1.905,-6.985) V15(3.175,-6.985) V16(4.445,-6.985) V17(5.715,-6.985) V18(6.985,-6.985) V19(8.255,-6.985) V20(9.525,-6.985) V21(10.795,-6.985) V22(12.065,-6.985) V23(13.335,-6.985) V24(14.605,-6.985) W1(-14.605,-8.255) W2(-13.335,-8.255) W3(-12.065,-8.255) W4(-10.795,-8.255) W5(-9.525,-8.255) W6(-8.255,-8.255) W7(-6.985,-8.255) W8(-5.715,-8.255) W9(-4.445,-8.255) W10(-3.175,-8.255) W11(-1.905,-8.255) W12(-0.635,-8.255) W13(0.635,-8.255) W14(1.905,-8.255) W15(3.175,-8.255) W16(4.445,-8.255) W17(5.715,-8.255) W18(6.985,-8.255) W19(8.255,-8.255) W20(9.525,-8.255) W21(10.795,-8.255) W22(12.065,-8.255) W23(13.335,-8.255) W24(14.605,-8.255) Y1(-14.605,-9.525) Y2(-13.335,-9.525) Y3(-12.065,-9.525) Y4(-10.795,-9.525) Y5(-9.525,-9.525) Y6(-8.255,-9.525) Y7(-6.985,-9.525) Y8(-5.715,-9.525) Y9(-4.445,-9.525) Y10(-3.175,-9.525) Y11(-1.905,-9.525) Y12(-0.635,-9.525) Y13(0.635,-9.525) Y14(1.905,-9.525) Y15(3.175,-9.525) Y16(4.445,-9.525) Y17(5.715,-9.525) Y18(6.985,-9.525) Y19(8.255,-9.525) Y20(9.525,-9.525) Y21(10.795,-9.525) Y22(12.065,-9.525) Y23(13.335,-9.525) Y24(14.605,-9.525)
Top Overlay:
  circle w0.25: c-16.15,14.605 r0.125
  region: -14.7,15.5 -15.5,14.7 -15.5,15.5
  lines w0.2: -15.5,14.7 -14.7,15.5 ; -15.5,-15.5 15.5,-15.5 15.5,15.5 -15.5,15.5 -15.5,-15.5
Mechanical 13:
  lines w0.1: -15.5,-15.5 15.5,-15.5 15.5,15.5 -15.5,15.5 -15.5,-15.5
Mechanical 15:
  lines w0.1: -0.5,0 0.5,0 ; 0,-0.5 0,0.5 ; -16.5,-16.5 16.5,-16.5 16.5,16.5 -16.5,16.5 -16.5,-16.5
3D body: height 2.6, standoff 0, extent -15.5,-15.5 15.5,15.5

## BGG728 [mm] "728-Ball Plastic Ball Grid Array (BGG728) - Pb-Free"
height 2.6
pads (728):
  round 0.6 smd: A2(-15.24,16.51) A3(-13.97,16.51) A4(-12.7,16.51) A5(-11.43,16.51) A6(-10.16,16.51) A7(-8.89,16.51) A8(-7.62,16.51) A9(-6.35,16.51) A10(-5.08,16.51) A11(-3.81,16.51) A12(-2.54,16.51) A13(-1.27,16.51) A14(0,16.51) A15(1.27,16.51) A16(2.54,16.51) A17(3.81,16.51) A18(5.08,16.51) A19(6.35,16.51) A20(7.62,16.51) A21(8.89,16.51) A22(10.16,16.51) A23(11.43,16.51) A24(12.7,16.51) A25(13.97,16.51) A26(15.24,16.51) A27(16.51,16.51) AA1(-16.51,-8.89) AA2(-15.24,-8.89) AA3(-13.97,-8.89) AA4(-12.7,-8.89) AA5(-11.43,-8.89) AA6(-10.16,-8.89) AA7(-8.89,-8.89) AA8(-7.62,-8.89) AA9(-6.35,-8.89) AA10(-5.08,-8.89) AA11(-3.81,-8.89) AA12(-2.54,-8.89) AA13(-1.27,-8.89) AA14(0,-8.89) AA15(1.27,-8.89) AA16(2.54,-8.89) AA17(3.81,-8.89) AA18(5.08,-8.89) AA19(6.35,-8.89) AA20(7.62,-8.89) AA21(8.89,-8.89) AA22(10.16,-8.89) AA23(11.43,-8.89) AA24(12.7,-8.89) AA25(13.97,-8.89) AA26(15.24,-8.89) AA27(16.51,-8.89) AB1(-16.51,-10.16) AB2(-15.24,-10.16) AB3(-13.97,-10.16) AB4(-12.7,-10.16) AB5(-11.43,-10.16) AB6(-10.16,-10.16) AB7(-8.89,-10.16) AB8(-7.62,-10.16) AB9(-6.35,-10.16) AB10(-5.08,-10.16) AB11(-3.81,-10.16) AB12(-2.54,-10.16) AB13(-1.27,-10.16) AB14(0,-10.16) AB15(1.27,-10.16) AB16(2.54,-10.16) AB17(3.81,-10.16) AB18(5.08,-10.16) AB19(6.35,-10.16) AB20(7.62,-10.16) AB21(8.89,-10.16) AB22(10.16,-10.16) AB23(11.43,-10.16) AB24(12.7,-10.16) AB25(13.97,-10.16) AB26(15.24,-10.16) AB27(16.51,-10.16) AC1(-16.51,-11.43) AC2(-15.24,-11.43) AC3(-13.97,-11.43) AC4(-12.7,-11.43) AC5(-11.43,-11.43) AC6(-10.16,-11.43) AC7(-8.89,-11.43) AC8(-7.62,-11.43) AC9(-6.35,-11.43) AC10(-5.08,-11.43) AC11(-3.81,-11.43) AC12(-2.54,-11.43) AC13(-1.27,-11.43) AC14(0,-11.43) AC15(1.27,-11.43) AC16(2.54,-11.43) AC17(3.81,-11.43) AC18(5.08,-11.43) AC19(6.35,-11.43) AC20(7.62,-11.43) AC21(8.89,-11.43) AC22(10.16,-11.43) AC23(11.43,-11.43) AC24(12.7,-11.43) AC25(13.97,-11.43) AC26(15.24,-11.43) AC27(16.51,-11.43) AD1(-16.51,-12.7) AD2(-15.24,-12.7) AD3(-13.97,-12.7) AD4(-12.7,-12.7) AD5(-11.43,-12.7) AD6(-10.16,-12.7) AD7(-8.89,-12.7) AD8(-7.62,-12.7) AD9(-6.35,-12.7) AD10(-5.08,-12.7) AD11(-3.81,-12.7) AD12(-2.54,-12.7) AD13(-1.27,-12.7) AD14(0,-12.7) AD15(1.27,-12.7) AD16(2.54,-12.7) AD17(3.81,-12.7) AD18(5.08,-12.7) AD19(6.35,-12.7) AD20(7.62,-12.7) AD21(8.89,-12.7) AD22(10.16,-12.7) AD23(11.43,-12.7) AD24(12.7,-12.7) AD25(13.97,-12.7) AD26(15.24,-12.7) AD27(16.51,-12.7) AE1(-16.51,-13.97) AE2(-15.24,-13.97) AE3(-13.97,-13.97) AE4(-12.7,-13.97) AE5(-11.43,-13.97) AE6(-10.16,-13.97) AE7(-8.89,-13.97) AE8(-7.62,-13.97) AE9(-6.35,-13.97) AE10(-5.08,-13.97) AE11(-3.81,-13.97) AE12(-2.54,-13.97) AE13(-1.27,-13.97) AE14(0,-13.97) AE15(1.27,-13.97) AE16(2.54,-13.97) AE17(3.81,-13.97) AE18(5.08,-13.97) AE19(6.35,-13.97) AE20(7.62,-13.97) AE21(8.89,-13.97) AE22(10.16,-13.97) AE23(11.43,-13.97) AE24(12.7,-13.97) AE25(13.97,-13.97) AE26(15.24,-13.97) AE27(16.51,-13.97) AF1(-16.51,-15.24) AF2(-15.24,-15.24) AF3(-13.97,-15.24) AF4(-12.7,-15.24) AF5(-11.43,-15.24) AF6(-10.16,-15.24) AF7(-8.89,-15.24) AF8(-7.62,-15.24) AF9(-6.35,-15.24) AF10(-5.08,-15.24) AF11(-3.81,-15.24) AF12(-2.54,-15.24) AF13(-1.27,-15.24) AF14(0,-15.24) AF15(1.27,-15.24) AF16(2.54,-15.24) AF17(3.81,-15.24) AF18(5.08,-15.24) AF19(6.35,-15.24) AF20(7.62,-15.24) AF21(8.89,-15.24) AF22(10.16,-15.24) AF23(11.43,-15.24) AF24(12.7,-15.24) AF25(13.97,-15.24) AF26(15.24,-15.24) AF27(16.51,-15.24) AG1(-16.51,-16.51) AG2(-15.24,-16.51) AG3(-13.97,-16.51) AG4(-12.7,-16.51) AG5(-11.43,-16.51) AG6(-10.16,-16.51) AG7(-8.89,-16.51) AG8(-7.62,-16.51) AG9(-6.35,-16.51) AG10(-5.08,-16.51) AG11(-3.81,-16.51) AG12(-2.54,-16.51) AG13(-1.27,-16.51) AG14(0,-16.51) AG15(1.27,-16.51) AG16(2.54,-16.51) AG17(3.81,-16.51) AG18(5.08,-16.51) AG19(6.35,-16.51) AG20(7.62,-16.51) AG21(8.89,-16.51) AG22(10.16,-16.51) AG23(11.43,-16.51) AG24(12.7,-16.51) AG25(13.97,-16.51) AG26(15.24,-16.51) AG27(16.51,-16.51) B1(-16.51,15.24) B2(-15.24,15.24) B3(-13.97,15.24) B4(-12.7,15.24) B5(-11.43,15.24) B6(-10.16,15.24) B7(-8.89,15.24) B8(-7.62,15.24) B9(-6.35,15.24) B10(-5.08,15.24) B11(-3.81,15.24) B12(-2.54,15.24) B13(-1.27,15.24) B14(0,15.24) B15(1.27,15.24) B16(2.54,15.24) B17(3.81,15.24) B18(5.08,15.24) B19(6.35,15.24) B20(7.62,15.24) B21(8.89,15.24) B22(10.16,15.24) B23(11.43,15.24) B24(12.7,15.24) B25(13.97,15.24) B26(15.24,15.24) B27(16.51,15.24) C1(-16.51,13.97) C2(-15.24,13.97) C3(-13.97,13.97) C4(-12.7,13.97) C5(-11.43,13.97) C6(-10.16,13.97) C7(-8.89,13.97) C8(-7.62,13.97) C9(-6.35,13.97) C10(-5.08,13.97) C11(-3.81,13.97) C12(-2.54,13.97) C13(-1.27,13.97) C14(0,13.97) C15(1.27,13.97) C16(2.54,13.97) C17(3.81,13.97) C18(5.08,13.97) C19(6.35,13.97) C20(7.62,13.97) C21(8.89,13.97) C22(10.16,13.97) C23(11.43,13.97) C24(12.7,13.97) C25(13.97,13.97) C26(15.24,13.97) C27(16.51,13.97) D1(-16.51,12.7) D2(-15.24,12.7) D3(-13.97,12.7) D4(-12.7,12.7) D5(-11.43,12.7) D6(-10.16,12.7) D7(-8.89,12.7) D8(-7.62,12.7) D9(-6.35,12.7) D10(-5.08,12.7) D11(-3.81,12.7) D12(-2.54,12.7) D13(-1.27,12.7) D14(0,12.7) D15(1.27,12.7) D16(2.54,12.7) D17(3.81,12.7) D18(5.08,12.7) D19(6.35,12.7) D20(7.62,12.7) D21(8.89,12.7) D22(10.16,12.7) D23(11.43,12.7) D24(12.7,12.7) D25(13.97,12.7) D26(15.24,12.7) D27(16.51,12.7) E1(-16.51,11.43) E2(-15.24,11.43) E3(-13.97,11.43) E4(-12.7,11.43) E5(-11.43,11.43) E6(-10.16,11.43) E7(-8.89,11.43) E8(-7.62,11.43) E9(-6.35,11.43) E10(-5.08,11.43) E11(-3.81,11.43) E12(-2.54,11.43) E13(-1.27,11.43) E14(0,11.43) E15(1.27,11.43) E16(2.54,11.43) E17(3.81,11.43) E18(5.08,11.43) E19(6.35,11.43) E20(7.62,11.43) E21(8.89,11.43) E22(10.16,11.43) E23(11.43,11.43) E24(12.7,11.43) E25(13.97,11.43) E26(15.24,11.43) E27(16.51,11.43) F1(-16.51,10.16) F2(-15.24,10.16) F3(-13.97,10.16) F4(-12.7,10.16) F5(-11.43,10.16) F6(-10.16,10.16) F7(-8.89,10.16) F8(-7.62,10.16) F9(-6.35,10.16) F10(-5.08,10.16) F11(-3.81,10.16) F12(-2.54,10.16) F13(-1.27,10.16) F14(0,10.16) F15(1.27,10.16) F16(2.54,10.16) F17(3.81,10.16) F18(5.08,10.16) F19(6.35,10.16) F20(7.62,10.16) F21(8.89,10.16) F22(10.16,10.16) F23(11.43,10.16) F24(12.7,10.16) F25(13.97,10.16) F26(15.24,10.16) F27(16.51,10.16) G1(-16.51,8.89) G2(-15.24,8.89) G3(-13.97,8.89) G4(-12.7,8.89) G5(-11.43,8.89) G6(-10.16,8.89) G7(-8.89,8.89) G8(-7.62,8.89) G9(-6.35,8.89) G10(-5.08,8.89) G11(-3.81,8.89) G12(-2.54,8.89) G13(-1.27,8.89) G14(0,8.89) G15(1.27,8.89) G16(2.54,8.89) G17(3.81,8.89) G18(5.08,8.89) G19(6.35,8.89) G20(7.62,8.89) G21(8.89,8.89) G22(10.16,8.89) G23(11.43,8.89) G24(12.7,8.89) G25(13.97,8.89) G26(15.24,8.89) G27(16.51,8.89) H1(-16.51,7.62) H2(-15.24,7.62) H3(-13.97,7.62) H4(-12.7,7.62) H5(-11.43,7.62) H6(-10.16,7.62) H7(-8.89,7.62) H8(-7.62,7.62) H9(-6.35,7.62) H10(-5.08,7.62) H11(-3.81,7.62) H12(-2.54,7.62) H13(-1.27,7.62) H14(0,7.62) H15(1.27,7.62) H16(2.54,7.62) H17(3.81,7.62) H18(5.08,7.62) H19(6.35,7.62) H20(7.62,7.62) H21(8.89,7.62) H22(10.16,7.62) H23(11.43,7.62) H24(12.7,7.62) H25(13.97,7.62) H26(15.24,7.62) H27(16.51,7.62) J1(-16.51,6.35) J2(-15.24,6.35) J3(-13.97,6.35) J4(-12.7,6.35) J5(-11.43,6.35) J6(-10.16,6.35) J7(-8.89,6.35) J8(-7.62,6.35) J9(-6.35,6.35) J10(-5.08,6.35) J11(-3.81,6.35) J12(-2.54,6.35) J13(-1.27,6.35) J14(0,6.35) J15(1.27,6.35) J16(2.54,6.35) J17(3.81,6.35) J18(5.08,6.35) J19(6.35,6.35) J20(7.62,6.35) J21(8.89,6.35) J22(10.16,6.35) J23(11.43,6.35) J24(12.7,6.35) J25(13.97,6.35) J26(15.24,6.35) J27(16.51,6.35) K1(-16.51,5.08) K2(-15.24,5.08) K3(-13.97,5.08) K4(-12.7,5.08) K5(-11.43,5.08) K6(-10.16,5.08) K7(-8.89,5.08) K8(-7.62,5.08) K9(-6.35,5.08) K10(-5.08,5.08) K11(-3.81,5.08) K12(-2.54,5.08) K13(-1.27,5.08) K14(0,5.08) K15(1.27,5.08) K16(2.54,5.08) K17(3.81,5.08) K18(5.08,5.08) K19(6.35,5.08) K20(7.62,5.08) K21(8.89,5.08) K22(10.16,5.08) K23(11.43,5.08) K24(12.7,5.08) K25(13.97,5.08) K26(15.24,5.08) K27(16.51,5.08) L1(-16.51,3.81) L2(-15.24,3.81) L3(-13.97,3.81) L4(-12.7,3.81) L5(-11.43,3.81) L6(-10.16,3.81) L7(-8.89,3.81) L8(-7.62,3.81) L9(-6.35,3.81) L10(-5.08,3.81) L11(-3.81,3.81) L12(-2.54,3.81) L13(-1.27,3.81) L14(0,3.81) L15(1.27,3.81) L16(2.54,3.81) L17(3.81,3.81) L18(5.08,3.81) L19(6.35,3.81) L20(7.62,3.81) L21(8.89,3.81) L22(10.16,3.81) L23(11.43,3.81) L24(12.7,3.81) L25(13.97,3.81) L26(15.24,3.81) L27(16.51,3.81) M1(-16.51,2.54) M2(-15.24,2.54) M3(-13.97,2.54) M4(-12.7,2.54) M5(-11.43,2.54) M6(-10.16,2.54) M7(-8.89,2.54) M8(-7.62,2.54) M9(-6.35,2.54) M10(-5.08,2.54) M11(-3.81,2.54) M12(-2.54,2.54) M13(-1.27,2.54) M14(0,2.54) M15(1.27,2.54) M16(2.54,2.54) M17(3.81,2.54) M18(5.08,2.54) M19(6.35,2.54) M20(7.62,2.54) M21(8.89,2.54) M22(10.16,2.54) M23(11.43,2.54) M24(12.7,2.54) M25(13.97,2.54) M26(15.24,2.54) M27(16.51,2.54) N1(-16.51,1.27) N2(-15.24,1.27) N3(-13.97,1.27) N4(-12.7,1.27) N5(-11.43,1.27) N6(-10.16,1.27) N7(-8.89,1.27) N8(-7.62,1.27) N9(-6.35,1.27) N10(-5.08,1.27) N11(-3.81,1.27) N12(-2.54,1.27) N13(-1.27,1.27) N14(0,1.27) N15(1.27,1.27) N16(2.54,1.27) N17(3.81,1.27) N18(5.08,1.27) N19(6.35,1.27) N20(7.62,1.27) N21(8.89,1.27) N22(10.16,1.27) N23(11.43,1.27) N24(12.7,1.27) N25(13.97,1.27) N26(15.24,1.27) N27(16.51,1.27) P1(-16.51,0) P2(-15.24,0) P3(-13.97,0) P4(-12.7,0) P5(-11.43,0) P6(-10.16,0) P7(-8.89,0) P8(-7.62,0) P9(-6.35,0) P10(-5.08,0) P11(-3.81,0) P12(-2.54,0) P13(-1.27,0) P14(0,0) P15(1.27,0) P16(2.54,0) P17(3.81,0) P18(5.08,0) P19(6.35,0) P20(7.62,0) P21(8.89,0) P22(10.16,0) P23(11.43,0) P24(12.7,0) P25(13.97,0) P26(15.24,0) P27(16.51,0) R1(-16.51,-1.27) R2(-15.24,-1.27) R3(-13.97,-1.27) R4(-12.7,-1.27) R5(-11.43,-1.27) R6(-10.16,-1.27) R7(-8.89,-1.27) R8(-7.62,-1.27) R9(-6.35,-1.27) R10(-5.08,-1.27) R11(-3.81,-1.27) R12(-2.54,-1.27) R13(-1.27,-1.27) R14(0,-1.27) R15(1.27,-1.27) R16(2.54,-1.27) R17(3.81,-1.27) R18(5.08,-1.27) R19(6.35,-1.27) R20(7.62,-1.27) R21(8.89,-1.27) R22(10.16,-1.27) R23(11.43,-1.27) R24(12.7,-1.27) R25(13.97,-1.27) R26(15.24,-1.27) R27(16.51,-1.27) T1(-16.51,-2.54) T2(-15.24,-2.54) T3(-13.97,-2.54) T4(-12.7,-2.54) T5(-11.43,-2.54) T6(-10.16,-2.54) T7(-8.89,-2.54) T8(-7.62,-2.54) T9(-6.35,-2.54) T10(-5.08,-2.54) T11(-3.81,-2.54) T12(-2.54,-2.54) T13(-1.27,-2.54) T14(0,-2.54) T15(1.27,-2.54) T16(2.54,-2.54) T17(3.81,-2.54) T18(5.08,-2.54) T19(6.35,-2.54) T20(7.62,-2.54) T21(8.89,-2.54) T22(10.16,-2.54) T23(11.43,-2.54) T24(12.7,-2.54) T25(13.97,-2.54) T26(15.24,-2.54) T27(16.51,-2.54) U1(-16.51,-3.81) U2(-15.24,-3.81) U3(-13.97,-3.81) U4(-12.7,-3.81) U5(-11.43,-3.81) U6(-10.16,-3.81) U7(-8.89,-3.81) U8(-7.62,-3.81) U9(-6.35,-3.81) U10(-5.08,-3.81) U11(-3.81,-3.81) U12(-2.54,-3.81) U13(-1.27,-3.81) U14(0,-3.81) U15(1.27,-3.81) U16(2.54,-3.81) U17(3.81,-3.81) U18(5.08,-3.81) U19(6.35,-3.81) U20(7.62,-3.81) U21(8.89,-3.81) U22(10.16,-3.81) U23(11.43,-3.81) U24(12.7,-3.81) U25(13.97,-3.81) U26(15.24,-3.81) U27(16.51,-3.81) V1(-16.51,-5.08) V2(-15.24,-5.08) V3(-13.97,-5.08) V4(-12.7,-5.08) V5(-11.43,-5.08) V6(-10.16,-5.08) V7(-8.89,-5.08) V8(-7.62,-5.08) V9(-6.35,-5.08) V10(-5.08,-5.08) V11(-3.81,-5.08) V12(-2.54,-5.08) V13(-1.27,-5.08) V14(0,-5.08) V15(1.27,-5.08) V16(2.54,-5.08) V17(3.81,-5.08) V18(5.08,-5.08) V19(6.35,-5.08) V20(7.62,-5.08) V21(8.89,-5.08) V22(10.16,-5.08) V23(11.43,-5.08) V24(12.7,-5.08) V25(13.97,-5.08) V26(15.24,-5.08) V27(16.51,-5.08) W1(-16.51,-6.35) W2(-15.24,-6.35) W3(-13.97,-6.35) W4(-12.7,-6.35) W5(-11.43,-6.35) W6(-10.16,-6.35) W7(-8.89,-6.35) W8(-7.62,-6.35) W9(-6.35,-6.35) W10(-5.08,-6.35) W11(-3.81,-6.35) W12(-2.54,-6.35) W13(-1.27,-6.35) W14(0,-6.35) W15(1.27,-6.35) W16(2.54,-6.35) W17(3.81,-6.35) W18(5.08,-6.35) W19(6.35,-6.35) W20(7.62,-6.35) W21(8.89,-6.35) W22(10.16,-6.35) W23(11.43,-6.35) W24(12.7,-6.35) W25(13.97,-6.35) W26(15.24,-6.35) W27(16.51,-6.35) Y1(-16.51,-7.62) Y2(-15.24,-7.62) Y3(-13.97,-7.62) Y4(-12.7,-7.62) Y5(-11.43,-7.62) Y6(-10.16,-7.62) Y7(-8.89,-7.62) Y8(-7.62,-7.62) Y9(-6.35,-7.62) Y10(-5.08,-7.62) Y11(-3.81,-7.62) Y12(-2.54,-7.62) Y13(-1.27,-7.62) Y14(0,-7.62) Y15(1.27,-7.62) Y16(2.54,-7.62) Y17(3.81,-7.62) Y18(5.08,-7.62) Y19(6.35,-7.62) Y20(7.62,-7.62) Y21(8.89,-7.62) Y22(10.16,-7.62) Y23(11.43,-7.62) Y24(12.7,-7.62) Y25(13.97,-7.62) Y26(15.24,-7.62) Y27(16.51,-7.62)
Top Overlay:
  circle w0.25: c-18.15,16.51 r0.125
  region: -16.51,17.5 -17.5,16.51 -17.5,17.5
  lines w0.2: -17.5,16.51 -16.51,17.5 ; -17.5,-17.5 17.5,-17.5 17.5,17.5 -17.5,17.5 -17.5,-17.5
Mechanical 13:
  lines w0.1: -17.5,-17.5 17.5,-17.5 17.5,17.5 -17.5,17.5 -17.5,-17.5
Mechanical 15:
  lines w0.1: -0.5,0 0.5,0 ; 0,-0.5 0,0.5 ; -18.5,-18.5 18.5,-18.5 18.5,18.5 -18.5,18.5 -18.5,-18.5
3D body: height 2.6, standoff 0, extent -17.5,-17.5 17.5,17.5

## CB100_L [mm] "100-Pin Ceramic Brazed Quad Flat Pack (CB100), IPC High Density"
height 3.5
pads (100):
  oval 0.4x1.9 smd: 1(0,11.3) 2(-0.635,11.3) 3(-1.27,11.3) 4(-1.905,11.3) 5(-2.54,11.3) 6(-3.175,11.3) 7(-3.81,11.3) 8(-4.445,11.3) 9(-5.08,11.3) 10(-5.715,11.3) 11(-6.35,11.3) 12(-6.985,11.3) 13(-7.62,11.3) 39(-7.62,-11.3) 40(-6.985,-11.3) 41(-6.35,-11.3) 42(-5.715,-11.3) 43(-5.08,-11.3) 44(-4.445,-11.3) 45(-3.81,-11.3) 46(-3.175,-11.3) 47(-2.54,-11.3) 48(-1.905,-11.3) 49(-1.27,-11.3) 50(-0.635,-11.3) 51(0,-11.3) 52(0.635,-11.3) 53(1.27,-11.3) 54(1.905,-11.3) 55(2.54,-11.3) 56(3.175,-11.3) 57(3.81,-11.3) 58(4.445,-11.3) 59(5.08,-11.3) 60(5.715,-11.3) 61(6.35,-11.3) 62(6.985,-11.3) 63(7.62,-11.3) 89(7.62,11.3) 90(6.985,11.3) 91(6.35,11.3) 92(5.715,11.3) 93(5.08,11.3) 94(4.445,11.3) 95(3.81,11.3) 96(3.175,11.3) 97(2.54,11.3) 98(1.905,11.3) 99(1.27,11.3) 100(0.635,11.3)
  oval 1.9x0.4 smd: 14(-11.3,7.62) 15(-11.3,6.985) 16(-11.3,6.35) 17(-11.3,5.715) 18(-11.3,5.08) 19(-11.3,4.445) 20(-11.3,3.81) 21(-11.3,3.175) 22(-11.3,2.54) 23(-11.3,1.905) 24(-11.3,1.27) 25(-11.3,0.635) 26(-11.3,0) 27(-11.3,-0.635) 28(-11.3,-1.27) 29(-11.3,-1.905) 30(-11.3,-2.54) 31(-11.3,-3.175) 32(-11.3,-3.81) 33(-11.3,-4.445) 34(-11.3,-5.08) 35(-11.3,-5.715) 36(-11.3,-6.35) 37(-11.3,-6.985) 38(-11.3,-7.62) 64(11.3,-7.62) 65(11.3,-6.985) 66(11.3,-6.35) 67(11.3,-5.715) 68(11.3,-5.08) 69(11.3,-4.445) 70(11.3,-3.81) 71(11.3,-3.175) 72(11.3,-2.54) 73(11.3,-1.905) 74(11.3,-1.27) 75(11.3,-0.635) 76(11.3,0) 77(11.3,0.635) 78(11.3,1.27) 79(11.3,1.905) 80(11.3,2.54) 81(11.3,3.175) 82(11.3,3.81) 83(11.3,4.445) 84(11.3,5.08) 85(11.3,5.715) 86(11.3,6.35) 87(11.3,6.985) 88(11.3,7.62)
Top Overlay:
  circle w0.25: c0,12.8 r0.125
  lines w0.2: -0.25,9.95 -0.25,8.45 0.25,8.45 0.25,9.95 ; -9.95,-7.62 -9.95,7.62 -7.62,9.95 7.62,9.95 9.95,7.62 9.95,-7.62 7.62,-9.95 -7.62,-9.95 -9.95,-7.62
Mechanical 13:
  lines w0.1: -9.555,-9.555 -9.555,9.555 9.555,9.555 9.555,-9.555 -9.555,-9.555
Mechanical 15:
  lines w0.1: -0.5,0 0.5,0 ; 0,-0.5 0,0.5 ; -12.35,-12.35 -12.35,12.35 12.35,12.35 12.35,-12.35 -12.35,-12.35
3D body: height 3.5, standoff 0, extent -9.555,-9.555 9.555,9.555

## CB100_M [mm] "100-Pin Ceramic Brazed Quad Flat Pack (CB100), IPC Low Density"
height 3.5
pads (100):
  oval 0.45x2.5 smd: 1(0,11.4) 2(-0.635,11.4) 3(-1.27,11.4) 4(-1.905,11.4) 5(-2.54,11.4) 6(-3.175,11.4) 7(-3.81,11.4) 8(-4.445,11.4) 9(-5.08,11.4) 10(-5.715,11.4) 11(-6.35,11.4) 12(-6.985,11.4) 13(-7.62,11.4) 39(-7.62,-11.4) 40(-6.985,-11.4) 41(-6.35,-11.4) 42(-5.715,-11.4) 43(-5.08,-11.4) 44(-4.445,-11.4) 45(-3.81,-11.4) 46(-3.175,-11.4) 47(-2.54,-11.4) 48(-1.905,-11.4) 49(-1.27,-11.4) 50(-0.635,-11.4) 51(0,-11.4) 52(0.635,-11.4) 53(1.27,-11.4) 54(1.905,-11.4) 55(2.54,-11.4) 56(3.175,-11.4) 57(3.81,-11.4) 58(4.445,-11.4) 59(5.08,-11.4) 60(5.715,-11.4) 61(6.35,-11.4) 62(6.985,-11.4) 63(7.62,-11.4) 89(7.62,11.4) 90(6.985,11.4) 91(6.35,11.4) 92(5.715,11.4) 93(5.08,11.4) 94(4.445,11.4) 95(3.81,11.4) 96(3.175,11.4) 97(2.54,11.4) 98(1.905,11.4) 99(1.27,11.4) 100(0.635,11.4)
  oval 2.5x0.45 smd: 14(-11.4,7.62) 15(-11.4,6.985) 16(-11.4,6.35) 17(-11.4,5.715) 18(-11.4,5.08) 19(-11.4,4.445) 20(-11.4,3.81) 21(-11.4,3.175) 22(-11.4,2.54) 23(-11.4,1.905) 24(-11.4,1.27) 25(-11.4,0.635) 26(-11.4,0) 27(-11.4,-0.635) 28(-11.4,-1.27) 29(-11.4,-1.905) 30(-11.4,-2.54) 31(-11.4,-3.175) 32(-11.4,-3.81) 33(-11.4,-4.445) 34(-11.4,-5.08) 35(-11.4,-5.715) 36(-11.4,-6.35) 37(-11.4,-6.985) 38(-11.4,-7.62) 64(11.4,-7.62) 65(11.4,-6.985) 66(11.4,-6.35) 67(11.4,-5.715) 68(11.4,-5.08) 69(11.4,-4.445) 70(11.4,-3.81) 71(11.4,-3.175) 72(11.4,-2.54) 73(11.4,-1.905) 74(11.4,-1.27) 75(11.4,-0.635) 76(11.4,0) 77(11.4,0.635) 78(11.4,1.27) 79(11.4,1.905) 80(11.4,2.54) 81(11.4,3.175) 82(11.4,3.81) 83(11.4,4.445) 84(11.4,5.08) 85(11.4,5.715) 86(11.4,6.35) 87(11.4,6.985) 88(11.4,7.62)
Top Overlay:
  circle w0.25: c0,13.2 r0.125
  lines w0.2: -0.25,9.75 -0.25,8.25 0.25,8.25 0.25,9.75 ; -9.75,-7.62 -9.75,7.62 -7.62,9.75 7.62,9.75 9.75,7.62 9.75,-7.62 7.62,-9.75 -7.62,-9.75 -9.75,-7.62
Mechanical 13:
  lines w0.1: -9.555,-9.555 -9.555,9.555 9.555,9.555 9.555,-9.555 -9.555,-9.555
Mechanical 15:
  lines w0.1: -0.5,0 0.5,0 ; 0,-0.5 0,0.5 ; -13.15,-13.15 -13.15,13.15 13.15,13.15 13.15,-13.15 -13.15,-13.15
3D body: height 3.5, standoff 0, extent -9.555,-9.555 9.555,9.555

## CB100_N [mm] "100-Pin Ceramic Brazed Quad Flat Pack (CB100), IPC Medium Density"
height 3.5
pads (100):
  oval 0.4x2.2 smd: 1(0,11.35) 2(-0.635,11.35) 3(-1.27,11.35) 4(-1.905,11.35) 5(-2.54,11.35) 6(-3.175,11.35) 7(-3.81,11.35) 8(-4.445,11.35) 9(-5.08,11.35) 10(-5.715,11.35) 11(-6.35,11.35) 12(-6.985,11.35) 13(-7.62,11.35) 39(-7.62,-11.35) 40(-6.985,-11.35) 41(-6.35,-11.35) 42(-5.715,-11.35) 43(-5.08,-11.35) 44(-4.445,-11.35) 45(-3.81,-11.35) 46(-3.175,-11.35) 47(-2.54,-11.35) 48(-1.905,-11.35) 49(-1.27,-11.35) 50(-0.635,-11.35) 51(0,-11.35) 52(0.635,-11.35) 53(1.27,-11.35) 54(1.905,-11.35) 55(2.54,-11.35) 56(3.175,-11.35) 57(3.81,-11.35) 58(4.445,-11.35) 59(5.08,-11.35) 60(5.715,-11.35) 61(6.35,-11.35) 62(6.985,-11.35) 63(7.62,-11.35) 89(7.62,11.35) 90(6.985,11.35) 91(6.35,11.35) 92(5.715,11.35) 93(5.08,11.35) 94(4.445,11.35) 95(3.81,11.35) 96(3.175,11.35) 97(2.54,11.35) 98(1.905,11.35) 99(1.27,11.35) 100(0.635,11.35)
  oval 2.2x0.4 smd: 14(-11.35,7.62) 15(-11.35,6.985) 16(-11.35,6.35) 17(-11.35,5.715) 18(-11.35,5.08) 19(-11.35,4.445) 20(-11.35,3.81) 21(-11.35,3.175) 22(-11.35,2.54) 23(-11.35,1.905) 24(-11.35,1.27) 25(-11.35,0.635) 26(-11.35,0) 27(-11.35,-0.635) 28(-11.35,-1.27) 29(-11.35,-1.905) 30(-11.35,-2.54) 31(-11.35,-3.175) 32(-11.35,-3.81) 33(-11.35,-4.445) 34(-11.35,-5.08) 35(-11.35,-5.715) 36(-11.35,-6.35) 37(-11.35,-6.985) 38(-11.35,-7.62) 64(11.35,-7.62) 65(11.35,-6.985) 66(11.35,-6.35) 67(11.35,-5.715) 68(11.35,-5.08) 69(11.35,-4.445) 70(11.35,-3.81) 71(11.35,-3.175) 72(11.35,-2.54) 73(11.35,-1.905) 74(11.35,-1.27) 75(11.35,-0.635) 76(11.35,0) 77(11.35,0.635) 78(11.35,1.27) 79(11.35,1.905) 80(11.35,2.54) 81(11.35,3.175) 82(11.35,3.81) 83(11.35,4.445) 84(11.35,5.08) 85(11.35,5.715) 86(11.35,6.35) 87(11.35,6.985) 88(11.35,7.62)
Top Overlay:
  circle w0.25: c0,13 r0.125
  lines w0.2: -0.25,9.85 -0.25,8.35 0.25,8.35 0.25,9.85 ; -9.85,-7.62 -9.85,7.62 -7.62,9.85 7.62,9.85 9.85,7.62 9.85,-7.62 7.62,-9.85 -7.62,-9.85 -9.85,-7.62
Mechanical 13:
  lines w0.1: -9.555,-9.555 -9.555,9.555 9.555,9.555 9.555,-9.555 -9.555,-9.555
Mechanical 15:
  lines w0.1: -0.5,0 0.5,0 ; 0,-0.5 0,0.5 ; -12.7,-12.7 -12.7,12.7 12.7,12.7 12.7,-12.7 -12.7,-12.7
3D body: height 3.5, standoff 0, extent -9.555,-9.555 9.555,9.555

## CB164_L [mm] "164-Pin Ceramic Brazed Quad Flat Pack (CB164), IPC High Density"
height 3.4
pads (164):
  oval 0.4x2 smd: 1(0,16.1) 2(-0.635,16.1) 3(-1.27,16.1) 4(-1.905,16.1) 5(-2.54,16.1) 6(-3.175,16.1) 7(-3.81,16.1) 8(-4.445,16.1) 9(-5.08,16.1) 10(-5.715,16.1) 11(-6.35,16.1) 12(-6.985,16.1) 13(-7.62,16.1) 14(-8.255,16.1) 15(-8.89,16.1) 16(-9.525,16.1) 17(-10.16,16.1) 18(-10.795,16.1) 19(-11.43,16.1) 20(-12.065,16.1) 21(-12.7,16.1) 63(-12.7,-16.1) 64(-12.065,-16.1) 65(-11.43,-16.1) 66(-10.795,-16.1) 67(-10.16,-16.1) 68(-9.525,-16.1) 69(-8.89,-16.1) 70(-8.255,-16.1) 71(-7.62,-16.1) 72(-6.985,-16.1) 73(-6.35,-16.1) 74(-5.715,-16.1) 75(-5.08,-16.1) 76(-4.445,-16.1) 77(-3.81,-16.1) 78(-3.175,-16.1) 79(-2.54,-16.1) 80(-1.905,-16.1) 81(-1.27,-16.1) 82(-0.635,-16.1) 83(0,-16.1) 84(0.635,-16.1) 85(1.27,-16.1) 86(1.905,-16.1) 87(2.54,-16.1) 88(3.175,-16.1) 89(3.81,-16.1) 90(4.445,-16.1) 91(5.08,-16.1) 92(5.715,-16.1) 93(6.35,-16.1) 94(6.985,-16.1) 95(7.62,-16.1) 96(8.255,-16.1) 97(8.89,-16.1) 98(9.525,-16.1) 99(10.16,-16.1) 100(10.795,-16.1) 101(11.43,-16.1) 102(12.065,-16.1) 103(12.7,-16.1) 145(12.7,16.1) 146(12.065,16.1) 147(11.43,16.1) 148(10.795,16.1) 149(10.16,16.1) 150(9.525,16.1) 151(8.89,16.1) 152(8.255,16.1) 153(7.62,16.1) 154(6.985,16.1) 155(6.35,16.1) 156(5.715,16.1) 157(5.08,16.1) 158(4.445,16.1) 159(3.81,16.1) 160(3.175,16.1) 161(2.54,16.1) 162(1.905,16.1) 163(1.27,16.1) 164(0.635,16.1)
  oval 2x0.4 smd: 22(-16.1,12.7) 23(-16.1,12.065) 24(-16.1,11.43) 25(-16.1,10.795) 26(-16.1,10.16) 27(-16.1,9.525) 28(-16.1,8.89) 29(-16.1,8.255) 30(-16.1,7.62) 31(-16.1,6.985) 32(-16.1,6.35) 33(-16.1,5.715) 34(-16.1,5.08) 35(-16.1,4.445) 36(-16.1,3.81) 37(-16.1,3.175) 38(-16.1,2.54) 39(-16.1,1.905) 40(-16.1,1.27) 41(-16.1,0.635) 42(-16.1,0) 43(-16.1,-0.635) 44(-16.1,-1.27) 45(-16.1,-1.905) 46(-16.1,-2.54) 47(-16.1,-3.175) 48(-16.1,-3.81) 49(-16.1,-4.445) 50(-16.1,-5.08) 51(-16.1,-5.715) 52(-16.1,-6.35) 53(-16.1,-6.985) 54(-16.1,-7.62) 55(-16.1,-8.255) 56(-16.1,-8.89) 57(-16.1,-9.525) 58(-16.1,-10.16) 59(-16.1,-10.795) 60(-16.1,-11.43) 61(-16.1,-12.065) 62(-16.1,-12.7) 104(16.1,-12.7) 105(16.1,-12.065) 106(16.1,-11.43) 107(16.1,-10.795) 108(16.1,-10.16) 109(16.1,-9.525) 110(16.1,-8.89) 111(16.1,-8.255) 112(16.1,-7.62) 113(16.1,-6.985) 114(16.1,-6.35) 115(16.1,-5.715) 116(16.1,-5.08) 117(16.1,-4.445) 118(16.1,-3.81) 119(16.1,-3.175) 120(16.1,-2.54) 121(16.1,-1.905) 122(16.1,-1.27) 123(16.1,-0.635) 124(16.1,0) 125(16.1,0.635) 126(16.1,1.27) 127(16.1,1.905) 128(16.1,2.54) 129(16.1,3.175) 130(16.1,3.81) 131(16.1,4.445) 132(16.1,5.08) 133(16.1,5.715) 134(16.1,6.35) 135(16.1,6.985) 136(16.1,7.62) 137(16.1,8.255) 138(16.1,8.89) 139(16.1,9.525) 140(16.1,10.16) 141(16.1,10.795) 142(16.1,11.43) 143(16.1,12.065) 144(16.1,12.7)
Top Overlay:
  circle w0.25: c0,17.65 r0.125
  lines w0.2: -0.25,14.7 -0.25,13.2 0.25,13.2 0.25,14.7 ; -14.7,-12.7 -14.7,12.7 -12.7,14.7 12.7,14.7 14.7,12.7 14.7,-12.7 12.7,-14.7 -12.7,-14.7 -14.7,-12.7
Mechanical 13:
  lines w0.1: -14.385,-14.385 -14.385,14.385 14.385,14.385 14.385,-14.385 -14.385,-14.385
Mechanical 15:
  lines w0.1: -0.5,0 0.5,0 ; 0,-0.5 0,0.5 ; -17.2,-17.2 -17.2,17.2 17.2,17.2 17.2,-17.2 -17.2,-17.2
3D body: height 3.4, standoff 0, extent -14.385,-14.385 14.385,14.385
